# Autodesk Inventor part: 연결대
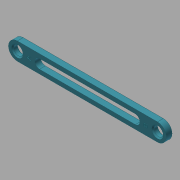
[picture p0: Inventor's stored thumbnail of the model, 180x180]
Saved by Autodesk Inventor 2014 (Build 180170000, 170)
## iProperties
Created: 2017-07
Part Number: 연결대
Material: 스테인리스강
Document SubType Name: Modeling
Designer: mduedu
Density: 8.08 g/cm^3
Appearance: 커뎃 파란색
Mass: 46.85 g
Surface Area: 49.3916 cm^2
Volume: 5.79826 cm^3
Author: mduedu
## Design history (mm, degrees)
sketch "스케치1"
  geometry: L1 (-67.5, 0)-(67.5, 0); L2 (-67.5, -7.5)-(67.5, -7.5); L3 (67.5, -7.5)-(67.5, 7.5); L4 (67.5, 7.5)-(-67.5, 7.5); L5 (-67.5, 7.5)-(-67.5, -7.5); L6 (-67.5, -7.5)-(67.5, 7.5); L7 (67.5, -7.5)-(-67.5, 7.5); 2 further points
  constraints: 14 end point, 4 midpoint, 2 horizontal, 2 parallel, 1 coincident, 1 perpendicular
  dimensions: "d0" = 135 distance of L1.start L1.end; "d2" = 15 distance of L2.end L3.end
extrude "돌출1" new body sketch "스케치1" distance "d3" = 5; taper "d4" = 0 deg
fillet "모깎기1"
fillet "모깎기2"
sketch "스케치2"
  geometry: C1 r 4 at (60, 0); A1 r 7.5 centre (60, 0) between (60, -7.5) and (60, 7.5) reference; 1 further point
  constraints: 1 centre point, 1 coincident
  dimensions: "d5" = 8 diameter of C1
extrude "돌출2" cut sketch "스케치2" stored distance "d6" = 10; taper "d7" = 0 deg
chamfer "모따기1" distance "d8" = 1; stored, may be unused: second distance "d9" = 2, angle "d10" = 45 deg
sketch "스케치3"
  geometry: L1 (-45, 0)-(45, 0); L2 (-45, -4)-(45, -4); L3 (45, -4)-(45, 4); L4 (45, 4)-(-45, 4); L5 (-45, 4)-(-45, -4); L6 (-45, -4)-(45, 4); L7 (45, -4)-(-45, 4); 2 further points
  constraints: 14 end point, 4 midpoint, 2 horizontal, 2 parallel, 1 coincident, 1 perpendicular
  dimensions: "d11" = 90 distance of L1.start L1.end; "d13" = 8 distance of L2.end L3.end
extrude "돌출3" cut sketch "스케치3" stored distance "d14" = 10; taper "d15" = 0 deg
fillet "모깎기3"
fillet "모깎기4"
sketch "스케치4"
  geometry: L1 (-60, 0)-(60, 0); C1 r 5 at (-60, 0) reference; C2 r 5 at (60, 0) reference; 3 further points
  constraints: 2 end point, 2 point on line, 1 horizontal, 2 other
  dimensions: "d16" = 50 distance of point (-50, 0) point (0, 0); "d17" = 50 distance of point (50, 0) point (0, 0)
feature "엠보싱1" sketch "스케치4" dims "d0" = 135, "d2" = 15, "d18" = 0.5, "d19" = 0
node "솔리드1"
mirror "대칭1"
